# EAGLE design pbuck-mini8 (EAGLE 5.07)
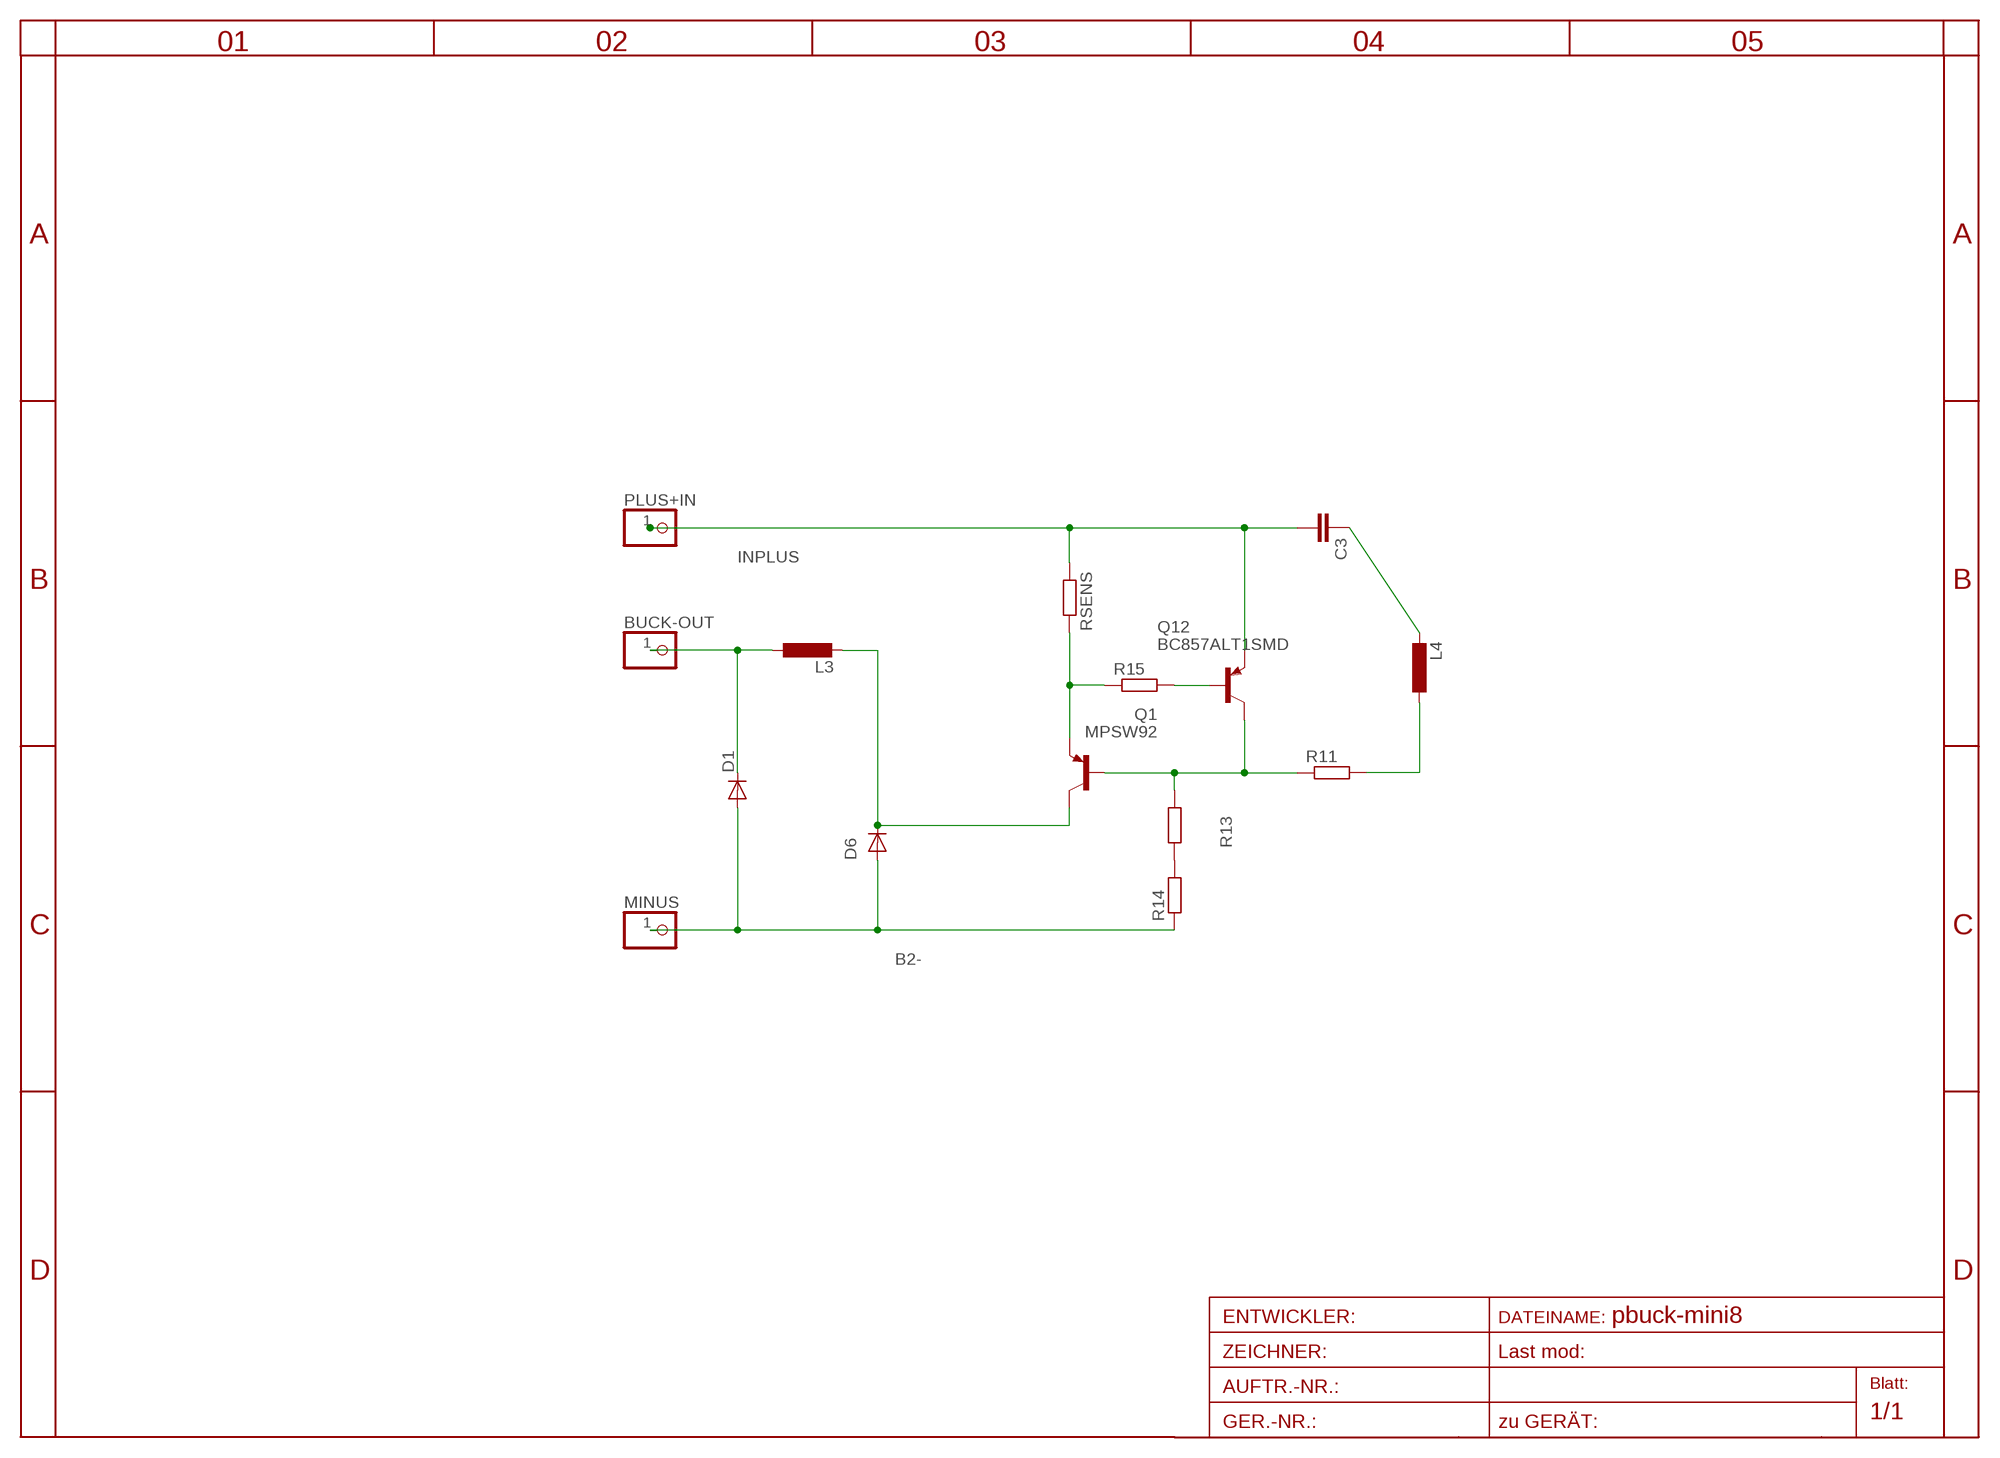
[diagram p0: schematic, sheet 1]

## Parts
BUCK-OUT  PINHD-1X11MM0  [1X1MM0]
C3  C-EUC0805  [C0805]
D1  DIODE-MINIMELF  [MINIMELF]
D6  DIODE-SMA-DO214  [SMA-DO214AC]
L3  L-EU0204/5  [0204/5]
L4  L-EU0204/5  [0204/5]
MINUS  PINHD-1X11MM0  [1X1MM0]
PLUS+IN  PINHD-1X11MM0  [1X1MM0]
Q1  MPSW92  [TO92-CBE]
Q12  BC857ALT1SMD  [SOT23-BEC]
R11  R-EU_R0805  [R0805]
R13  R-EU_R1206  [R1206]
R14  R-EU_R1206  [R1206]
R15  R-EU_R0805  [R0805]
RSENS  R-EU_R1206  [R1206]

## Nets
B2-: D1.A D6.A MINUS.1 R14.1
B92: Q1.B Q12.C R11.1 R13.1
B_OUT: BUCK-OUT.1 D1.C L3.1
C92: D6.K(C) L3.2 Q1.C
EB: Q1.E R15.1 RSENS.2
INPLUS: C3.2 PLUS+IN.1 Q12.E RSENS.1
L4DOT: C3.1 L4.2
L4NO: L4.1 R11.2
N$11: R13.2 R14.2
N$12: Q12.B R15.2

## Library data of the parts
BUCK-OUT MINUS PLUS+IN = pinhead:PINHD-1X1: PIN HEADER
C3 = rcl:C-EU: CAPACITOR, European symbol
D1 D6 = diode:DIODE-: DIODE
L3 L4 = rcl:L-EU: INDUCTOR, European symbol
Q1 = transistor-pnp:MPSW92*: PNP Transistror
Q12 = transistor-pnp:BC857*: PNP Transistror
R11 R13-R15 RSENS = rcl:R-EU_: RESISTOR, European symbol

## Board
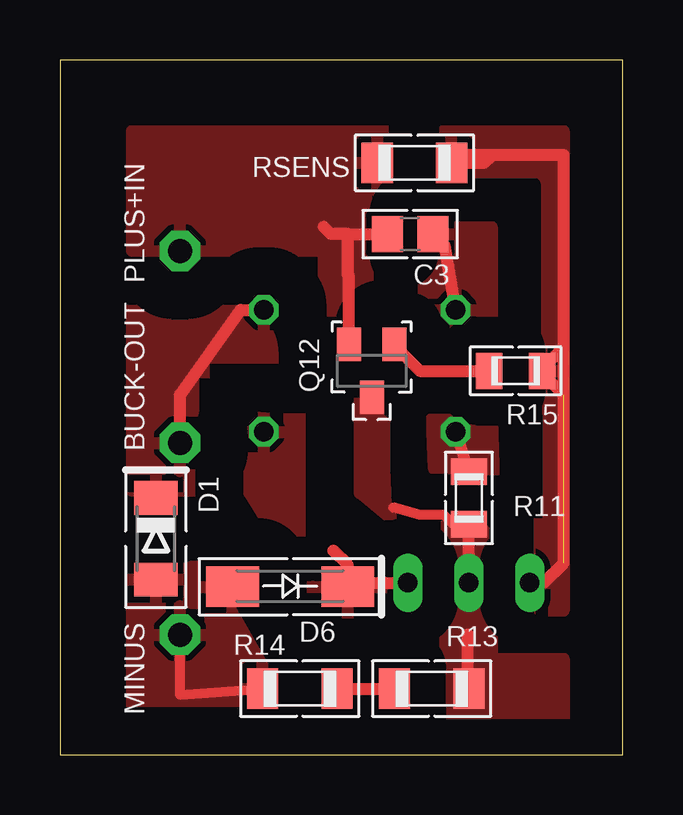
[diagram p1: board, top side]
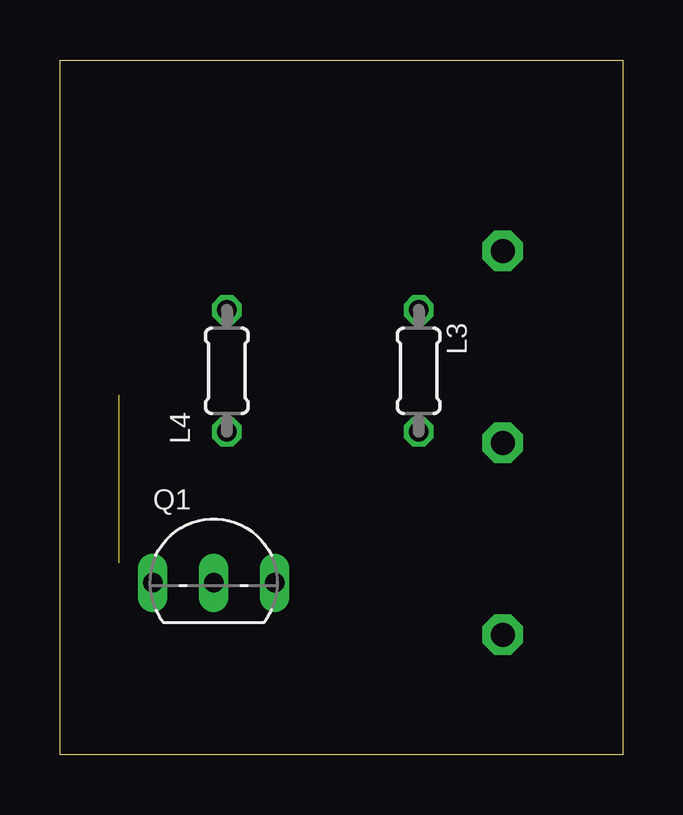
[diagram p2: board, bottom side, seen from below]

Size 23.46 x 28.96 mm. Coordinates in mm from the lower left corner, seen from the top.
Outline: 0,0 23.46,0 23.46,28.96 0,28.96 0,0
Copper layers (1*16): Top 0.035mm / dielectric 1.5mm / Bottom 0.035mm
Design rules "default *": minimum track width 10mil, minimum drill 20mil, track to track 8mil, track to pad 8mil, pad to pad 8mil, via to via 8mil, smd to smd 8mil, copper to edge 40mil, drill to drill 8mil, minimum pad ring 8mil, minimum via ring 8mil, stop-mask expansion 4mil, vias tented up to drill 0mil, thermal gap 10mil

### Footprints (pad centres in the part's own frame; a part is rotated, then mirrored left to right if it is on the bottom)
1X1MM0 = drill 1 pad 1.676 octagon: 1 0,0
C0805 = smd 1.3 x 1.5: 1 -0.95,0; 2 0.95,0
MINIMELF = smd 1.4 x 1.8: A 1.7,0; C -1.7,0
SMA-DO214AC = smd 2.2 x 1.7: A 2.4,0; K -2.4,0
0204/5 = drill 0.813 octagon: 1 -2.54,0; 2 2.54,0
TO92-CBE = drill 0.813 long: B 0,0; C 2.54,0; E -2.54,0
SOT23-BEC = smd 1 x 1.4: B -0.95,-1.1; C 0,1.1; E 0.95,-1.1
R0805 = smd 1.1 x 1.5: 1 -1.1,0; 2 1.1,0
R1206 = smd 1.3 x 1.7: 1 -1.55,0; 2 1.55,0

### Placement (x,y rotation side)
BUCK-OUT  5,13 0 top
C3  14.6,21.7 180 top
D1  4,9 270 top
D6  9.6,7 180 top
L3  8.5,16 270 bottom
L4  16.5,16 90 bottom
MINUS  5,5 0 top
PLUS+IN  5,21 0 top
Q1  17.05,7.16 0 bottom
Q12  13,16 180 top
R11  17.05,10.7 90 top
R13  15.5,2.75 180 top
R14  10,2.75 0 top
R15  19,16 180 top
RSENS  14.78,24.67 0 top

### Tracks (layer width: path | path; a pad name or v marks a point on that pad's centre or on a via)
B2-
  Top 0.406: R14.1 5,2.5 MINUS.1
  pour Top (isolate 2, rank 2): 3,8 6,8 10,1 3,1
B92
  Top 0.406: R11.1 16.4,9.6 16,10 15,10 13.9,10.3
  Top 0.5: 17,5 17,3.49 R13.1 | Q1.B R11.1
  pour Top (isolate 1.5, rank 2, no thermals): 12.5,14.9 18,9 18,4 21,4 21,1 16,1 16,8 12.5,10.9
B_OUT
  Top 0.5: L3.1 7.54,18.54 5,15 BUCK-OUT.1
  pour Top (isolate 2, rank 4): 3,19 10,19 11,18 7,11 3,11
C92
  Top 0.5: Q1.C 12.16,7.16 D6.K 12,7.9 11.4,8.5
  pour Top (isolate 2, rank 3): 9,14 11,14 11,11 12,9 13,9 14.2,8.5 14.2,5.9 11,5.9 7.9,10.9 7.9,14.1
EB  (1 unrouted)
  Top 0.5: 18,25 17.67,24.67 RSENS.2 16.66,25 21,25 21,8 20.16,7.16 Q1.E | 21,17 20.1,16.1 R15.1 20.1,15.9 21,15
  pour Top (isolate 1.8, rank 2): 16,26 21,26 21,6 20,6 20,24 16,24
INPLUS
  Top 0.5: Q12.E 12.05,19.95 12,20 12,21.7 | 12,21.7 11.3,21.7 11,22 | 12,21.7 C3.2
  pour Top (isolate 2): 3,26 14,26 13,17 11,17 11,21 3,21
L4DOT
  Top 0.5: L4.2 16.05,21.2 C3.1
  pour Top (isolate 1.5): 15,22 18,22 18,18 15,18
L4NO
  Top 0.5: R11.2 L4.1
  pour Top (isolate 1.5, no thermals): 15.5,14 18,14 18.1,11.4 15.6,11.9
N$11
  Top 0.5: R14.2 R13.2
N$12
  Top 0.5: Q12.B 13.95,17.05 15,16 R15.2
